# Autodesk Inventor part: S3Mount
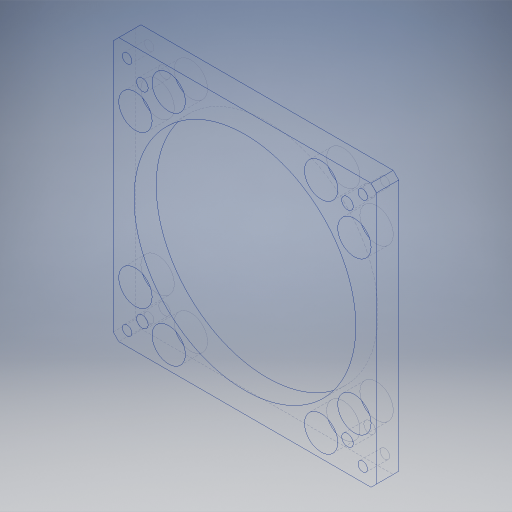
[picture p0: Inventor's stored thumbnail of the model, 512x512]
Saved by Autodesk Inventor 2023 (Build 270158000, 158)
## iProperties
Created: 2024-01
Part Number: S3Mount
Material: Aluminum 6061
Document SubType Name: Modeling
Designer: tornqvih
Density: 2.7 g/cm^3
Appearance: Aluminum - Flat
Author: tornqvih
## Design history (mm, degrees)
sketch "Sketch1" dims "d3" = 0
  geometry: L1 (-47.5, 47.5)-(47.5, 47.5); L2 (47.5, 47.5)-(47.5, -47.5); L3 (47.5, -47.5)-(-47.5, -47.5); L4 (-47.5, -47.5)-(-47.5, 47.5); L5 (-47.5, 47.5)-(47.5, -47.5); L6 (47.5, 47.5)-(-47.5, -47.5); L7 (0, -66.5)-(0, 66.5) reference; L8 (-66.5, 0)-(66.5, 0) reference; C1 r 6 at (-27.5, 39.5); C2 r 6 at (-39.5, 27.5); C3 r 6 at (27.5, 39.5); C4 r 6 at (39.5, 27.5); C5 r 6 at (-39.5, -27.5); C6 r 6 at (-27.5, -39.5); C7 r 6 at (27.5, -39.5); C8 r 6 at (39.5, -27.5); C9 r 40 at (0, 0); 1 further point
  constraints: 12 end point, 9 centre point, 7 equal radius, 7 symmetric about line, 2 midpoint, 2 parallel, 1 coincident, 1 horizontal, 1 perpendicular
  dimensions: "d0" = 95 distance of L1.start L1.end; "d1" = 95 distance of L3.end L1.start; "d15" = 12 diameter of C1; "d16" = 8 distance from line of L1 C1.centre; "d17" = 12 horizontal distance of C2.centre C1.centre; "d34" = 80 diameter of C9
extrude "Extrusion1" new body sketch "Sketch1" distance "d2" = 8; taper "d3" = 0 deg
sketch "Sketch2"
  geometry: L1 (0, -66.5)-(0, 66.5) reference; L2 (-66.5, 0)-(66.5, 0) reference; 5 further points
  constraints: 3 symmetric about line
  dimensions: "d4" = 85 distance of point (42.5, 42.5) point (-42.5, 42.5); "d5" = 85 distance of point (-42.5, -42.5) point (-42.5, 42.5)
hole "Hole1" sketch "Sketch2" at (-42.5, 42.5), (42.5, 42.5), (42.5, -42.5), (-42.5, -42.5) diameter "d6" = 3.4; stored, may be unused: countersink angle "d10" = 90 deg, drill point angle "d12" = 118 deg; dims "d7" = 6, "d8" = 4, "d9" = 2, "d11" = 3
sketch "Sketch3"
  geometry: L1 (0, -66.5)-(0, 66.5) reference; L2 (-66.5, 0)-(66.5, 0) reference; L3 (47.5, 47.5)-(-47.5, 47.5) reference; L4 (-47.5, 47.5)-(-47.5, -47.5) reference; 5 further points
  constraints: 3 symmetric about line
  dimensions: "d35" = 37 distance from line of L1 point (-37, 37); "d36" = 37 distance from line of L2 point (-37, 37)
hole "Hole2" sketch "Sketch3" at (-37, 37), (37, 37), (37, -37), (-37, -37) diameter "d20" = 4.134; stored, may be unused: countersink angle "d24" = 90 deg, drill point angle "d26" = 118 deg; dims "d21" = 10, "d22" = 4, "d23" = 2, "d25" = 8.8
chamfer "Chamfer1" distance "d31" = 2; stored, may be unused: second distance "d32" = 2, angle "d33" = 45 deg
body "Solid1"
